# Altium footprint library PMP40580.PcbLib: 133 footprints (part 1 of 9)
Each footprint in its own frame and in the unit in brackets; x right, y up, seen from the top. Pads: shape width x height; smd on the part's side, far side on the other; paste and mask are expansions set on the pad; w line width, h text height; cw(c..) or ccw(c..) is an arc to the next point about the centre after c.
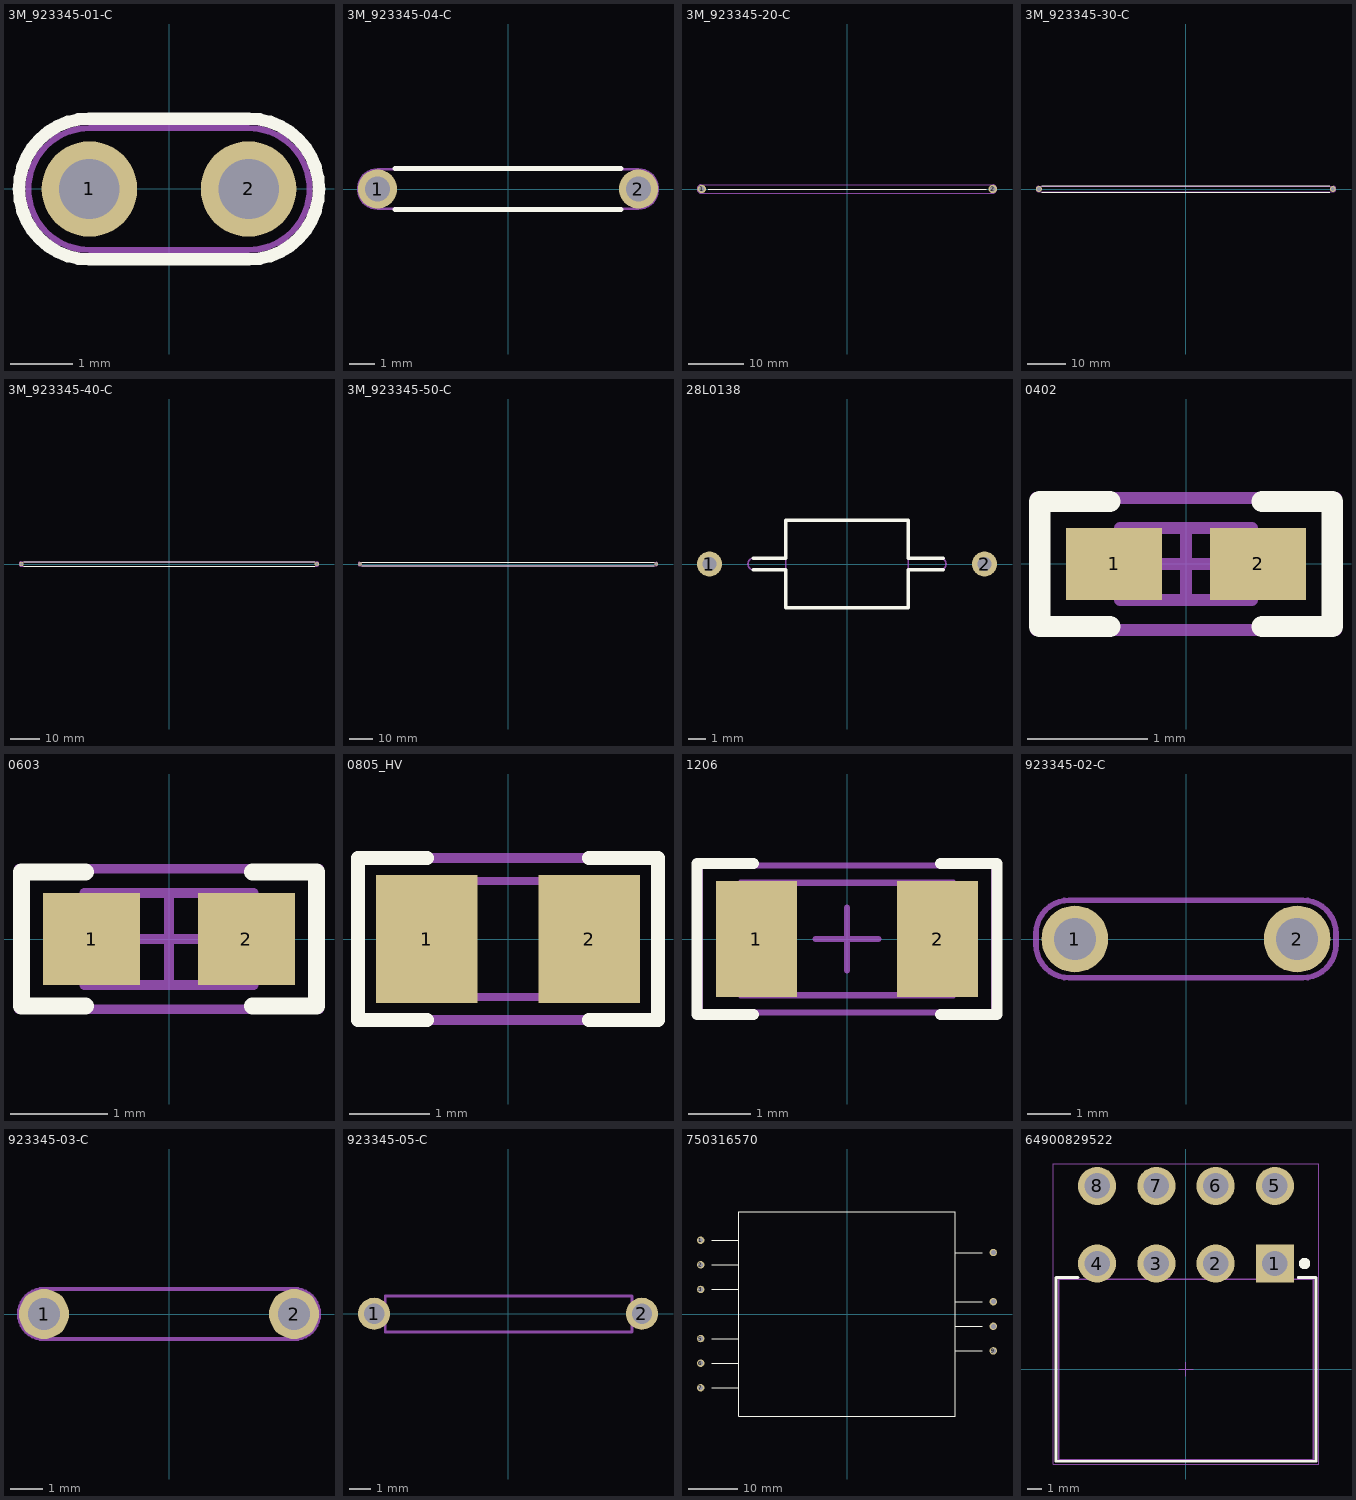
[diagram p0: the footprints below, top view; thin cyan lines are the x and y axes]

## 3M_923345-01-C [mil] "Wire Jumper"
height 90
pads (2):
  round 60 hole 38: 1(-50,0) 2(50,0)
Top Overlay:
  lines w7.87: -49.99,-44.3 cw(c-50,0) -49.99,44.3 49.99,44.3 cw(c50,0) 49.99,-44.3 -49.99,-44.3
Mechanical 5:
  lines w3.94: 49.99,-38.39 ccw(c49.99,0) 49.99,38.39 -49.99,38.39 ccw(c-49.99,0) -49.99,-38.39 49.99,-38.37
  text ".Designator" at -43.31,-7.87 h23.62
3D body "3M_923345-01-c.stp": height 74.31, standoff -150, extent -62.69,-12.67 62.71,12.68

## 3M_923345-04-C [mil] "Jumper Wire, 400 mil Spacing, Yellow, Pkg of 200"
height 80
pads (2):
  round 60 hole 38: 1(-200,0) 2(200,0)
Top Overlay:
  lines w7.87: -173.23,-31.5 173.23,-31.5 ; -173.23,31.5 173.23,31.5
Mechanical 5:
  lines w3.94: -200,-30 cw(c-200,0) -200,30 200,30 cw(c200,0) 200,-30 -200,-30
  text ".Designator" at -60,-20 h40
3D body: height 79.76, standoff 20, extent -180,-29.94 180,29.94
3D body: height 64.88, standoff 35, extent -200,-14.97 200,14.97
3D body: height 50, standoff -98.43, extent -214.88,-14.96 -185,14.98
3D body: height 50, standoff -98.43, extent 185,-14.97 214.88,14.97
3D body: height 65, standoff 35, extent 185.16,-14.93 215,14.94
3D body: height 65, standoff 35, extent -214.85,-14.89 -185.01,14.98

## 3M_923345-20-C [mil] "Jumper Wire, 2\" Spacing, Red, Pkg of 100"
height 80
pads (2):
  round 60 hole 38: 1(-1031.5,0) 2(1031.5,0)
Top Overlay:
  lines w7.87: -984.25,0 984.25,0
Bottom Overlay:
  lines w7.87: -984.25,0 984.25,0
Mechanical 5:
  lines w3.94: -1035.43,-30 cw(c-1035.43,0) -1035.43,30 ; -1031.5,-30 1031.5,-30 ; -1031.5,30 1031.5,30 ; 1029.92,-30 ccw(c1029.92,0) 1029.92,30
  text ".Designator" at -51.18,-19.68 h40
3D body: height 61.72, standoff 38.19, extent -1031.49,-11.79 1031.5,11.79
3D body: height 50, standoff -98.43, extent -1043.21,-11.78 -1019.68,11.8
3D body: height 50, standoff -98.43, extent 1018.11,-11.79 1041.64,11.79
3D body: height 61.81, standoff 38.19, extent 1018.12,-11.72 1041.74,11.73
3D body: height 61.81, standoff 38.19, extent -1043.3,-11.72 -1019.68,11.73

## 3M_923345-30-C [mil] "Jumper Wire, 3\" Spacing, Orange, Pkg of 75"
height 80
pads (2):
  round 60 hole 38: 1(-1500,0) 2(1500,0)
Top Overlay:
  lines w7.87: -1470,-32 1470,-32 ; -1470,32 1470,32
Mechanical 5:
  lines w3.94: -1500,-30 cw(c-1500,0) -1500,30 ; -1496.06,-30 1503.94,-30 ; -1496.06,30 1500,30 ; 1502.36,-30 ccw(c1502.36,0) 1502.36,30
  text ".Designator" at -59.06,-19.68 h40
3D body: height 64.88, standoff 35, extent -1500,-14.97 1500,14.97
3D body: height 79.27, standoff 20.5, extent -1472.44,-27.39 1467.56,31.5
3D body: height 65, standoff 35, extent -1514.98,-14.86 -1485.01,14.94
3D body: height 65, standoff 35, extent 1487.52,-14.93 1517.37,14.94
3D body: height 50, standoff -98.43, extent 1487.36,-14.97 1517.24,14.97
3D body: height 50, standoff -98.43, extent -1514.88,-14.96 -1485,14.98

## 3M_923345-40-C [mil] "Jumper Wire, 4\" Spacing, Yellow, Pkg of 75"
height 80
pads (2):
  round 60 hole 38: 1(-2000,0) 2(2000,0)
Top Overlay:
  lines w7.87: -1970,-32 1970,-32 ; -1970,32 1970,32
Mechanical 5:
  lines w3.94: -2003.94,-30 cw(c-2003.94,0) -2003.94,30 ; -2000,-30 2000,-30 ; -2000,30 2000,30 ; 1998.43,-30 ccw(c1998.43,0) 1998.43,30
  text ".Designator" at -51.18,-19.68 h40
3D body: height 79.27, standoff 20.5, extent -1973,-29 1967,29.89
3D body: height 64.88, standoff 35, extent -2000,-14.97 2000,14.97
3D body: height 50, standoff -98.43, extent 1985,-14.97 2014.88,14.97
3D body: height 65, standoff 35, extent 1985.04,-14.89 2015,14.91
3D body: height 65, standoff 35, extent -2014.84,-14.93 -1984.99,14.94
3D body: height 50, standoff -98.43, extent -2014.88,-14.96 -1985,14.98

## 3M_923345-50-C [mil] "Jumper Wire, 5\" Spacing, Green, Pkg of 75"
height 80
pads (2):
  round 60 hole 38: 1(-2500,0) 2(2500,0)
Top Overlay:
  lines w7.87: -2470,-32 2470,-32 ; -2470,32 2470,32
Mechanical 5:
  lines w3.94: -2504.94,-30 cw(c-2504.94,0) -2504.94,30 ; -2500,-30 2500,-30 ; -2500,30 2500,30 ; 2498.43,-30 ccw(c2498.43,0) 2498.43,30
  text ".Designator" at -51.18,-19.68 h40
3D body: height 79.27, standoff 20.5, extent -2473,-29 2467,29.88
3D body: height 64.88, standoff 35, extent -2500,-14.97 2500,14.97
3D body: height 50, standoff -98.43, extent 2485,-14.97 2514.88,14.97
3D body: height 65, standoff 35, extent 2485.04,-14.89 2515,14.91
3D body: height 65, standoff 35, extent -2515.84,-14.93 -2485.99,14.94
3D body: height 50, standoff -98.43, extent -2515.88,-14.96 -2486,14.98

## 28L0138 [mm] "TH, 2-Leads, Dia 3.51mm"
height 3.76
pads (2):
  round 1.45 hole 0.8: 1(-8,0) 2(8,0)
Top Overlay:
  lines w0.2: -5.461,-0.345 -3.556,-0.345 -3.556,-2.54 3.556,-2.54 3.556,-0.345 5.588,-0.345 ; -5.461,0.345 -3.556,0.345 -3.556,2.54 3.556,2.54 3.556,0.345 5.588,0.345 ; 4.634,-0.345 5.08,-0.345
Mechanical 5:
  lines w0.1: -3.62,-0.345 -4.38,-0.345 -5.415,-0.345 cw(c-5.415,0) -5.415,0.345 -4.38,0.345 -3.62,0.345 ; 3.62,-0.345 4.38,-0.345 5.415,-0.345 ccw(c5.415,0) 5.415,0.345 4.38,0.345 3.62,0.345 ; -3.556,-2.54 -3.556,2.54 3.429,2.54 3.556,2.54 3.556,-2.54 -3.556,-2.54
  text ".Designator" at -2,-1.3 h1.02

## 0402 [mm] "0402 from SM-752 data"
height 0.6
pads (2):
  rect 0.8x0.6 smd: 1(-0.6,0) 2(0.6,0)
Top Overlay:
  lines w0.178: -0.635,-0.521 -1.219,-0.521 -1.219,0.521 -0.635,0.521 ; 0.635,-0.521 1.219,-0.521 1.219,0.521 0.635,0.521
Mechanical 5:
  lines w0.1: -1.25,-0.55 1.25,-0.55 1.25,0.55 -1.25,0.55 -1.25,-0.55
  text ".Designator" at -1.117,-0.305 h0.61
Mechanical 13:
  lines w0.1: -0.35,-0.3 -0.35,0.3 ; 0.35,-0.3 0.35,0.3 ; -0.55,-0.3 -0.55,0.3 0.55,0.3 0.55,-0.3 -0.55,-0.3
Mechanical 15:
  lines w0.1: -0.3,0 0.3,0 ; 0,-0.3 0,0.3 ; -1.25,-0.55 -1.25,0.55 1.25,0.55 1.25,-0.55 -1.25,-0.55
3D body: height 0.6, standoff 0, extent -0.549,-0.299 -0.351,0.299
3D body: height 0.6, standoff 0, extent -0.349,-0.299 0.349,0.299
3D body: height 0.6, standoff 0, extent 0.351,-0.299 0.549,0.299

## 0603 [mm] "0603 from SM-752 data"
height 1
pads (2):
  rect 1x0.95 smd: 1(-0.8,0) 2(0.8,0)
Top Overlay:
  lines w0.178: -0.864,-0.691 -1.524,-0.691 -1.524,0.693 -0.864,0.693 ; 0.864,-0.691 1.524,-0.691 1.524,0.693 0.864,0.693
Mechanical 5:
  lines w0.1: -1.55,-0.725 -1.55,0.725 1.55,0.725 1.55,-0.725 -1.55,-0.725
  text ".Designator" at -1.397,-0.381 h0.76
Mechanical 13:
  lines w0.1: -0.55,-0.475 -0.55,0.475 ; 0.55,-0.475 0.55,0.475 ; -0.875,-0.475 0.875,-0.475 0.875,0.475 -0.875,0.475 -0.875,-0.475
Mechanical 15:
  lines w0.1: -0.475,0 0.475,0 ; 0,-0.475 0,0.475 ; -1.55,-0.725 1.55,-0.725 1.55,0.725 -1.55,0.725 -1.55,-0.725
3D body: height 1, standoff 0, extent -0.874,-0.474 -0.551,0.474
3D body: height 1, standoff 0, extent -0.549,-0.474 0.549,0.474
3D body: height 1, standoff 0, extent 0.551,-0.474 0.874,0.474

## 0805_HV [mil] "0805 with 30mil clearance between pads"
height 57.09
pads (2):
  rect 50x63 smd: 1(-40,0) 2(40,0)
Top Overlay:
  lines w7: -40,-40 -74,-40 -74,0 -74,40 -40,40 ; 40,-40 74,-40 74,0 74,40 40,40
Mechanical 5:
  lines w5: -74,-40 -74,40 74,40 74,-40 -74,-40
  text ".Designator" at -64,-17 h35
Mechanical 13:
  lines w3.94: -25.59,-28.54 -25.59,28.54 ; 25.59,-28.54 25.59,28.54 ; -43.31,-28.54 -43.31,28.54 43.31,28.54 43.31,-28.54 -43.31,-28.54
3D body: height 57.09, standoff 0, extent 25.61,-28.52 43.29,28.52
3D body: height 57.09, standoff 0, extent -25.57,-28.52 25.57,28.52
3D body: height 57.09, standoff 0, extent -43.29,-28.52 -25.61,28.52

## 1206 [mm] "1206 from SM-752 data"
height 1.35
pads (2):
  rect 1.3x1.85 smd: 1(-1.45,0) 2(1.45,0)
Top Overlay:
  lines w0.178: -1.5,-1.21 -2.4,-1.21 -2.4,1.21 -1.5,1.21 ; 1.5,-1.21 2.4,-1.21 2.4,1.21 1.5,1.21
Mechanical 5:
  lines w0.1: -1.7,-0.9 1.7,-0.9 1.7,0.9 -1.7,0.9 -1.7,-0.9
  text ".Designator" at -1.475,-0.4 h0.81
Mechanical 13:
  lines w0.1: -1.2,-0.9 -1.2,0.9 ; 1.2,-0.9 1.2,0.9 ; -1.7,-0.9 1.7,-0.9 1.7,0.9 -1.7,0.9 -1.7,-0.9
Mechanical 15:
  lines w0.1: -0.5,0 0.5,0 ; 0,-0.5 0,0.5 ; -2.35,-1.175 2.35,-1.175 2.35,1.175 -2.35,1.175 -2.35,-1.175
3D body: height 1.35, standoff 0, extent -1.699,-0.899 -1.201,0.899
3D body: height 1.35, standoff 0, extent -1.199,-0.899 1.199,0.899
3D body: height 1.35, standoff 0, extent 1.201,-0.899 1.699,0.899

## 923345-02-C [mil] "Wire Jumper"
height 90
pads (2):
  round 60 hole 38: 1(-100,0) 2(100,0)
Mechanical 5:
  lines w5: -135,-5 ccw(c-105,-5) -105,-35 0,-35 105,-35 ccw(c105,-5) 135,-5 135,5 ccw(c105,5) 105,35 0,35 -105,35 ccw(c-105,5) -135,5 -135,-5
  text ".Designator" at -70,-20 h40
3D body "923345-02-C.stp": height 99.7, standoff -150, extent -112.7,-36.62 112.7,40

## 923345-03-C [mil] "Wire Jumper"
height 90
pads (2):
  round 60 hole 38: 1(-150,0) 2(150,0)
Mechanical 5:
  lines w5: -180,0 cw(c-150,0) -150,30 0,30 150,30 cw(c150,0) 180,0 cw(c150,0) 150,-30 0,-30 -150,-30 cw(c-150,0) -180,0
  text ".Designator" at -80,-20 h40
3D body "923345-03-C.stp": height 99.7, standoff -150, extent -162.7,-40 162.7,36.62

## 923345-05-C [mil] "Wire Jumper 500mil"
height 90
pads (2):
  round 60 hole 38: 1(-250,0) 2(250,0)
Mechanical 5:
  lines w5: -229,-13.23 -248.69,-13.23 cw(c-248.69,-0.54) -261.38,-0.53 cw(c-248.69,-0.54) -248.68,12.16 -229,12.16 ; 231.63,-13.23 251.31,-13.23 ccw(c251.31,-0.54) 264.01,-0.54 ccw(c251.31,-0.54) 251.31,12.16 231.63,12.16 ; -229,-34 231.63,-34 231.63,32.93 -229,32.93 -229,-34
  text ".Designator" at -80,-20 h40
3D body "923345-05-c.stp": height 70.5, standoff -200, extent -262.69,-33.39 262.71,33.4

## 750316570 [mm] "TH, 5-Leads, Body 26.16x26.16mm"
height 19.05
pads (10):
  round 1.5 hole 1: 1(-29.75,15) 2(-29.75,10) 3(-29.75,5) 5(-29.75,-5) 6(-29.75,-10) 7(-29.75,-15) 9(29.75,-7.5) 10(29.75,-2.5) 11(29.75,2.5) 13(29.75,12.5)
Top Overlay:
  lines w0.254: -27.5,-15 -22,-15 ; -27.5,-10 -22,-10 ; -27.5,-5 -22,-5 ; -27.5,5 -22,5 ; -27.5,10 -22,10 ; -27.5,15 -22,15 ; 22,-7.5 27.5,-7.5 ; 22,-2.5 27.5,-2.5 ; 22,2.5 27.5,2.5 ; 22,12.5 27.5,12.5 ; -22,-20.75 -22,20.75 22,20.75 22,-20.75 -22,-20.75

## 64900829522 [mm] "4.20mm Male Dual Row Angled Header, 8p"
height 10
pads (8):
  rect 2.7x2.7 hole 1.8: 1(6.3,7.5)
  round 2.7 hole 1.8: 2(2.1,7.5) 3(-2.1,7.5) 4(-6.3,7.5) 5(6.3,13) 6(2.1,13) 7(-2.1,13) 8(-6.3,13)
Top Overlay:
  circle w0.4: c8.4,7.5 r0.2
  lines w0.2: -7.65,6.5 -9.2,6.5 -9.2,-6.5 9.2,-6.5 9.2,6.5 7.95,6.5
Mechanical 13:
  lines w0.1: -9,-6.4 9,-6.4 9,6.4 -9,6.4 -9,-6.4
Mechanical 15:
  lines w0.05: -0.5,0 0.5,0 ; 0,-0.5 0,0.5 ; -9.4,-6.7 -9.4,14.55 9.4,14.55 9.4,-6.7 -9.4,-6.7
3D body "64900829522.stp": height 11.43, standoff -3.47, extent -9,-6.4 9.32,13.57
